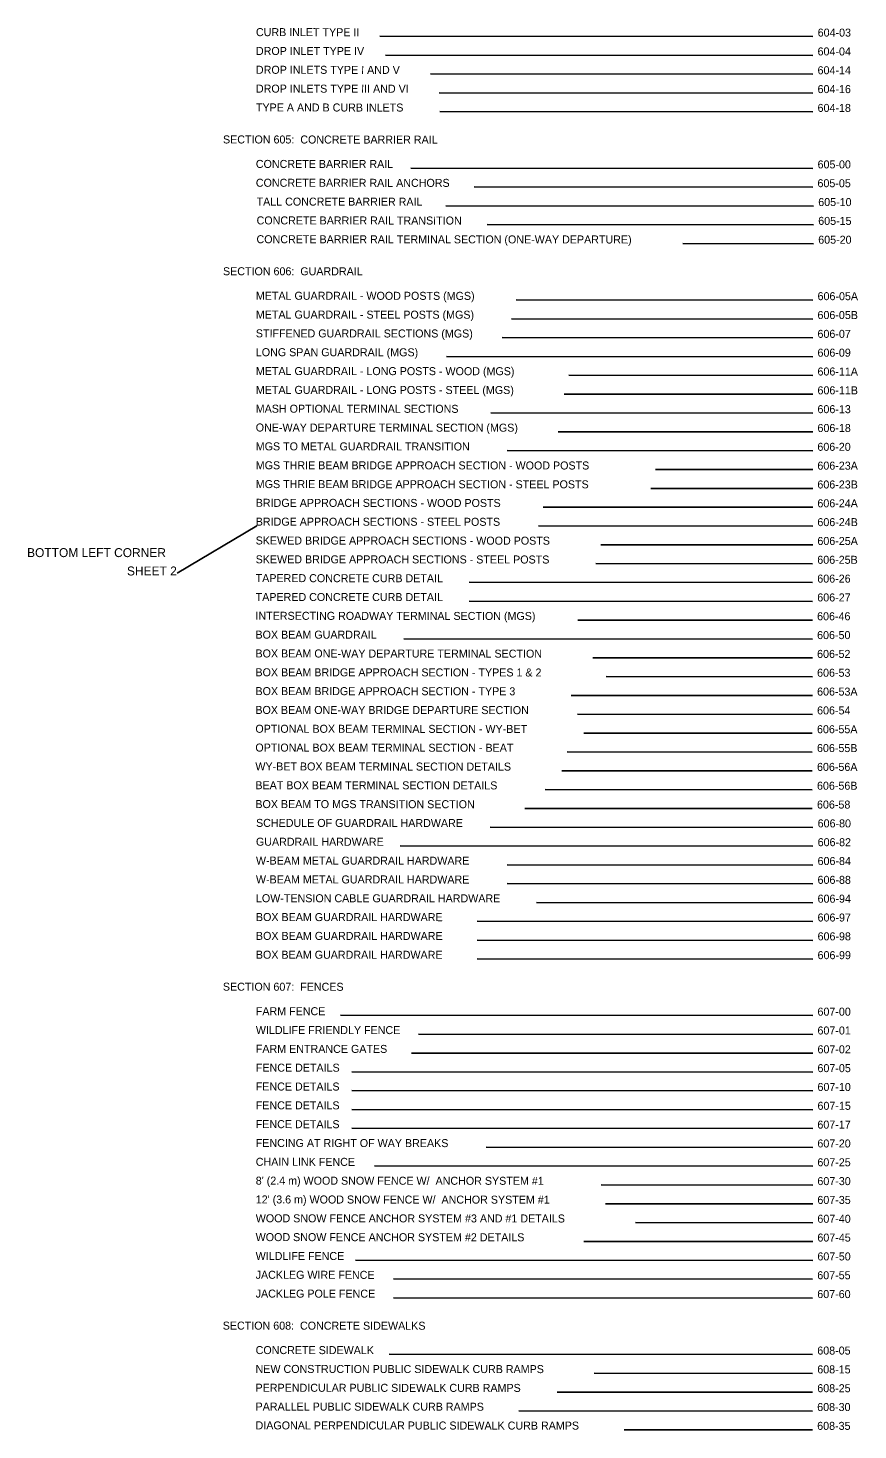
# Model space of a CAD drawing. Extents: x 49987.3 to 50007.6, y 49951 to 50011.
# Drawn here: x 49998.75 to 50007.57, y 49981.16 to 49996.05 of the extents above; entities that cross this region are included whole.
import ezdxf

# ---------------------------------------------------------------- set-up
doc = ezdxf.new("R2010")
doc.units = 0
doc.layers.add('Default', color=7, linetype='Continuous')
doc.layers.add('Level 1', color=7, linetype='Continuous')

msp = doc.modelspace()

# ---------------------------------------------------------------- linework, layer by layer
at = {"layer": 'Default'}
for p in [(50001.184, 49990.763), (50000.336, 49990.262)]:
    msp.add_line(p, (50000.336, 49990.262), dxfattribs=at)
at = {"layer": 'Level 1'}
for p, q in [((50002.489, 49995.964), (50007.09, 49995.96)), ((50002.549, 49995.764), (50007.089, 49995.76)), ((50003.028, 49995.563), (50007.089, 49995.56)), ((50003.118, 49995.363), (50007.089, 49995.36)), ((50003.128, 49995.163), (50007.089, 49995.16)), ((50002.819, 49994.563), (50007.089, 49994.56)), ((50003.491, 49994.363), (50007.088, 49994.36)), ((50003.189, 49994.163), (50007.096, 49994.16)), ((50003.63, 49993.963), (50007.096, 49993.96)), ((50005.707, 49993.761), (50007.096, 49993.76)), ((50003.937, 49993.163), (50007.089, 49993.16)), ((50003.887, 49992.963), (50007.088, 49992.96)), ((50003.788, 49992.763), (50007.088, 49992.76)), ((50003.198, 49992.563), (50007.088, 49992.56)), ((50004.495, 49992.362), (50007.088, 49992.36)), ((50004.448, 49992.162), (50007.088, 49992.16)), ((50003.667, 49991.963), (50007.088, 49991.96)), ((50004.382, 49991.762), (50007.088, 49991.76)), ((50003.84, 49991.563), (50007.087, 49991.56)), ((50005.419, 49991.361), (50007.087, 49991.36)), ((50005.367, 49991.161), (50007.087, 49991.16)), ((50004.225, 49990.962), (50007.087, 49990.96)), ((50004.173, 49990.762), (50007.087, 49990.76)), ((50004.836, 49990.562), (50007.087, 49990.56)), ((50004.785, 49990.362), (50007.086, 49990.36)), ((50003.437, 49990.163), (50007.086, 49990.16)), ((50003.437, 49989.963), (50007.086, 49989.96)), ((50004.594, 49989.762), (50007.084, 49989.76)), ((50002.744, 49989.563), (50007.084, 49989.56)), ((50004.753, 49989.362), (50007.084, 49989.36)), ((50004.892, 49989.162), (50007.084, 49989.16)), ((50004.52, 49988.962), (50007.084, 49988.96)), ((50004.588, 49988.762), (50007.084, 49988.76)), ((50004.656, 49988.562), (50007.083, 49988.56)), ((50004.479, 49988.362), (50007.083, 49988.36)), ((50004.423, 49988.162), (50007.083, 49988.16)), ((50004.246, 49987.962), (50007.083, 49987.96)), ((50004.031, 49987.762), (50007.083, 49987.76)), ((50003.662, 49987.563), (50007.09, 49987.56)), ((50002.705, 49987.363), (50007.09, 49987.36)), ((50003.843, 49987.163), (50007.089, 49987.16)), ((50003.843, 49986.963), (50007.089, 49986.96)), ((50004.152, 49986.762), (50007.089, 49986.76)), ((50003.524, 49986.563), (50007.089, 49986.56)), ((50003.523, 49986.363), (50007.089, 49986.36)), ((50003.523, 49986.163), (50007.089, 49986.16)), ((50002.07, 49985.564), (50007.088, 49985.56)), ((50002.901, 49985.363), (50007.088, 49985.36)), ((50002.826, 49985.163), (50007.088, 49985.16)), ((50002.191, 49984.964), (50007.088, 49984.96)), ((50002.191, 49984.764), (50007.088, 49984.76)), ((50002.191, 49984.564), (50007.088, 49984.56)), ((50002.19, 49984.364), (50007.087, 49984.36)), ((50003.617, 49984.163), (50007.087, 49984.16)), ((50002.432, 49983.964), (50007.087, 49983.96)), ((50004.84, 49983.762), (50007.087, 49983.76)), ((50004.887, 49983.562), (50007.087, 49983.56)), ((50005.205, 49983.362), (50007.087, 49983.36)), ((50004.655, 49983.162), (50007.087, 49983.16)), ((50002.232, 49982.964), (50007.087, 49982.96)), ((50002.633, 49982.764), (50007.086, 49982.76)), ((50002.636, 49982.563), (50007.086, 49982.56)), ((50002.588, 49981.964), (50007.086, 49981.96)), ((50004.765, 49981.762), (50007.086, 49981.76)), ((50004.374, 49981.562), (50007.086, 49981.56)), ((50003.964, 49981.363), (50007.085, 49981.36)), ((50005.085, 49981.162), (50007.085, 49981.16))]:
    msp.add_line(p, q, dxfattribs=at)

# ---------------------------------------------------------------- texts
at = {"layer": 'Default'}
for s, p in [('BOTTOM LEFT CORNER ', (49998.742, 49990.431)), ('SHEET 2', (49999.803, 49990.236))]:
    msp.add_text(s, height=0.095, dxfattribs=at).set_placement(p)
at = {"layer": 'Level 1'}
for s, p in [('CURB INLET TYPE II', (50001.173, 49995.965)), ('604-03', (50007.14, 49995.96)), ('DROP INLET TYPE IV', (50001.173, 49995.765)), ('604-04', (50007.139, 49995.76)), ('DROP INLETS TYPE I AND V', (50001.173, 49995.565)), ('604-14', (50007.139, 49995.56)), ('DROP INLETS TYPE III AND VI', (50001.173, 49995.365)), ('604-16', (50007.139, 49995.36)), ('TYPE A AND B CURB INLETS', (50001.173, 49995.165)), ('604-18', (50007.139, 49995.16)), ('SECTION 605:  CONCRETE BARRIER RAIL', (50000.823, 49994.825)), ('CONCRETE BARRIER RAIL', (50001.172, 49994.565)), ('605-00', (50007.139, 49994.56)), ('CONCRETE BARRIER RAIL ANCHORS', (50001.172, 49994.365)), ('605-05', (50007.138, 49994.36)), ('TALL CONCRETE BARRIER RAIL', (50001.18, 49994.165)), ('605-10', (50007.146, 49994.16)), ('CONCRETE BARRIER RAIL TRANSITION', (50001.18, 49993.965)), ('605-15', (50007.146, 49993.96)), ('CONCRETE BARRIER RAIL TERMINAL SECTION (ONE-WAY DEPARTURE)', (50001.179, 49993.765)), ('605-20', (50007.146, 49993.76)), ('SECTION 606:  GUARDRAIL', (50000.823, 49993.425)), ('METAL GUARDRAIL - WOOD POSTS (MGS)   ', (50001.172, 49993.165)), ('606-05A', (50007.139, 49993.16)), ('METAL GUARDRAIL - STEEL POSTS (MGS)   ', (50001.172, 49992.965)), ('606-05B', (50007.138, 49992.96)), ('STIFFENED GUARDRAIL SECTIONS (MGS)', (50001.172, 49992.765)), ('606-07', (50007.138, 49992.76)), ('LONG SPAN GUARDRAIL (MGS)', (50001.172, 49992.565)), ('606-09', (50007.138, 49992.56)), ('METAL GUARDRAIL - LONG POSTS - WOOD (MGS) ', (50001.172, 49992.365)), ('606-11A', (50007.138, 49992.36)), ('METAL GUARDRAIL - LONG POSTS - STEEL (MGS)', (50001.172, 49992.165)), ('606-11B', (50007.138, 49992.16)), ('MASH OPTIONAL TERMINAL SECTIONS', (50001.171, 49991.965)), ('606-13 ', (50007.138, 49991.96)), ('ONE-WAY DEPARTURE TERMINAL SECTION (MGS) ', (50001.171, 49991.765)), ('606-18', (50007.138, 49991.76)), ('MGS TO METAL GUARDRAIL TRANSITION        ', (50001.171, 49991.565)), ('606-20', (50007.137, 49991.56)), ('MGS THRIE BEAM BRIDGE APPROACH SECTION - WOOD POSTS', (50001.171, 49991.364)), ('606-23A', (50007.137, 49991.36)), ('MGS THRIE BEAM BRIDGE APPROACH SECTION - STEEL POSTS', (50001.171, 49991.164)), ('606-23B', (50007.137, 49991.16)), ('BRIDGE APPROACH SECTIONS - WOOD POSTS', (50001.171, 49990.965)), ('606-24A', (50007.137, 49990.96)), ('BRIDGE APPROACH SECTIONS - STEEL POSTS', (50001.171, 49990.765)), ('606-24B', (50007.137, 49990.76)), ('SKEWED BRIDGE APPROACH SECTIONS - WOOD POSTS', (50001.17, 49990.565)), ('606-25A', (50007.137, 49990.56)), ('SKEWED BRIDGE APPROACH SECTIONS - STEEL POSTS', (50001.17, 49990.365)), ('606-25B', (50007.136, 49990.36)), ('TAPERED CONCRETE CURB DETAIL', (50001.17, 49990.165)), ('606-26', (50007.136, 49990.16)), ('TAPERED CONCRETE CURB DETAIL', (50001.17, 49989.965)), ('606-27', (50007.136, 49989.96)), ('INTERSECTING ROADWAY TERMINAL SECTION (MGS)', (50001.168, 49989.765)), ('606-46', (50007.134, 49989.76)), ('BOX BEAM GUARDRAIL', (50001.168, 49989.565)), ('606-50', (50007.134, 49989.56)), ('BOX BEAM ONE-WAY DEPARTURE TERMINAL SECTION', (50001.168, 49989.365)), ('606-52', (50007.134, 49989.36)), ('BOX BEAM BRIDGE APPROACH SECTION - TYPES 1 & 2', (50001.168, 49989.165)), ('606-53', (50007.134, 49989.16)), ('BOX BEAM BRIDGE APPROACH SECTION - TYPE 3', (50001.168, 49988.965)), ('606-53A', (50007.134, 49988.96)), ('BOX BEAM ONE-WAY BRIDGE DEPARTURE SECTION', (50001.167, 49988.765)), ('606-54', (50007.134, 49988.76)), ('OPTIONAL BOX BEAM TERMINAL SECTION - WY-BET ', (50001.167, 49988.565)), ('606-55A', (50007.133, 49988.56)), ('OPTIONAL BOX BEAM TERMINAL SECTION - BEAT', (50001.167, 49988.365)), ('606-55B', (50007.133, 49988.36)), ('WY-BET BOX BEAM TERMINAL SECTION DETAILS', (50001.167, 49988.165)), ('606-56A', (50007.133, 49988.16)), ('BEAT BOX BEAM TERMINAL SECTION DETAILS', (50001.167, 49987.965)), ('606-56B', (50007.133, 49987.96)), ('BOX BEAM TO MGS TRANSITION SECTION', (50001.167, 49987.765)), ('606-58', (50007.133, 49987.76)), ('SCHEDULE OF GUARDRAIL HARDWARE', (50001.174, 49987.565)), ('606-80', (50007.14, 49987.56)), ('GUARDRAIL HARDWARE', (50001.173, 49987.365)), ('606-82', (50007.14, 49987.36)), ('W-BEAM METAL GUARDRAIL HARDWARE', (50001.173, 49987.165)), ('606-84', (50007.139, 49987.16)), ('W-BEAM METAL GUARDRAIL HARDWARE', (50001.173, 49986.965)), ('606-88', (50007.139, 49986.96)), ('LOW-TENSION CABLE GUARDRAIL HARDWARE', (50001.173, 49986.765)), ('606-94', (50007.139, 49986.76)), ('BOX BEAM GUARDRAIL HARDWARE', (50001.173, 49986.565)), ('606-97', (50007.139, 49986.56)), ('BOX BEAM GUARDRAIL HARDWARE', (50001.173, 49986.365)), ('606-98', (50007.139, 49986.36)), ('BOX BEAM GUARDRAIL HARDWARE', (50001.172, 49986.165)), ('606-99', (50007.139, 49986.16)), ('SECTION 607:  FENCES', (50000.822, 49985.825)), ('FARM FENCE', (50001.172, 49985.565)), ('607-00', (50007.138, 49985.56)), ('WILDLIFE FRIENDLY FENCE', (50001.172, 49985.365)), ('607-01', (50007.138, 49985.36)), ('FARM ENTRANCE GATES', (50001.172, 49985.165)), ('607-02', (50007.138, 49985.16)), ('FENCE DETAILS', (50001.172, 49984.965)), ('607-05', (50007.138, 49984.96)), ('FENCE DETAILS', (50001.171, 49984.765)), ('607-10', (50007.138, 49984.76)), ('FENCE DETAILS  ', (50001.171, 49984.565)), ('607-15', (50007.138, 49984.56)), ('FENCE DETAILS  ', (50001.171, 49984.365)), ('607-17', (50007.137, 49984.36)), ('FENCING AT RIGHT OF WAY BREAKS', (50001.171, 49984.165)), ('607-20', (50007.137, 49984.16)), ('CHAIN LINK FENCE', (50001.171, 49983.965)), ('607-25', (50007.137, 49983.96)), ("8' (2.4 m) WOOD SNOW FENCE W/  ANCHOR SYSTEM #1", (50001.171, 49983.765)), ('607-30', (50007.137, 49983.76)), ("12' (3.6 m) WOOD SNOW FENCE W/  ANCHOR SYSTEM #1", (50001.171, 49983.565)), ('607-35', (50007.137, 49983.56)), ('WOOD SNOW FENCE ANCHOR SYSTEM #3 AND #1 DETAILS', (50001.171, 49983.365)), ('607-40', (50007.137, 49983.36)), ('WOOD SNOW FENCE ANCHOR SYSTEM #2 DETAILS', (50001.17, 49983.165)), ('607-45', (50007.137, 49983.16)), ('WILDLIFE FENCE', (50001.17, 49982.965)), ('607-50', (50007.137, 49982.96)), ('JACKLEG WIRE FENCE', (50001.17, 49982.765)), ('607-55', (50007.136, 49982.76)), ('JACKLEG POLE FENCE', (50001.17, 49982.565)), ('607-60', (50007.136, 49982.56)), ('SECTION 608:  CONCRETE SIDEWALKS', (50000.82, 49982.225)), ('CONCRETE SIDEWALK', (50001.17, 49981.965)), ('608-05', (50007.136, 49981.96)), ('NEW CONSTRUCTION PUBLIC SIDEWALK CURB RAMPS', (50001.169, 49981.765)), ('608-15', (50007.136, 49981.76)), ('PERPENDICULAR PUBLIC SIDEWALK CURB RAMPS', (50001.169, 49981.565)), ('608-25', (50007.136, 49981.56)), ('PARALLEL PUBLIC SIDEWALK CURB RAMPS', (50001.169, 49981.365)), ('608-30', (50007.135, 49981.36)), ('DIAGONAL PERPENDICULAR PUBLIC SIDEWALK CURB RAMPS', (50001.169, 49981.165)), ('608-35', (50007.135, 49981.16))]:
    msp.add_text(s, height=0.085, rotation=359.9586, dxfattribs=at).set_placement(p)

doc.saveas('drawing.dxf')
